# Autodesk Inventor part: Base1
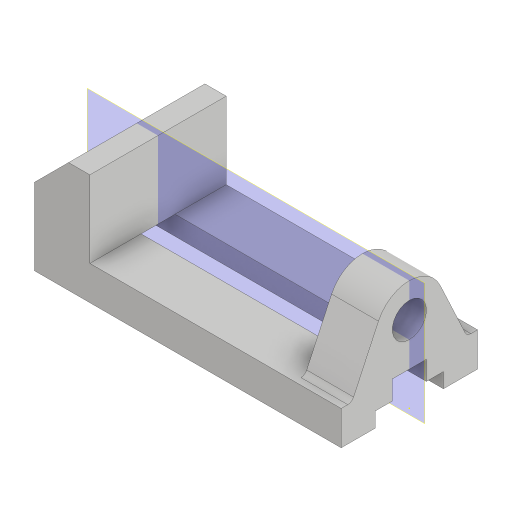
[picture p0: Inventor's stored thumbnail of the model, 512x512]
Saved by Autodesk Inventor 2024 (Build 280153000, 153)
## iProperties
Created: 2016-03
Part Number: Base1
Material: Generic
Document SubType Name: Modeling
Designer: Sandeep
Density: 1 g/cm^3
Appearance: Default
Author: Sandeep
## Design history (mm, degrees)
sketch "Sketch1"
  geometry: L1 (0, 0)-(0, 16); L2 (0, 16)-(118, 16); L3 (118, 16)-(118, 52); L4 (118, 52)-(144, 52); L5 (144, 52)-(144, 0); L6 (144, 0)-(0, 0)
  constraints: 12 end point, 3 perpendicular, 1 vertical
  dimensions: "d1" = 144 distance of L5.end L1.start; "d2" = 26 distance of L3.end L4.end; "d3" = 16 distance between parallel lines of L6 L2; "d4" = 36 distance between parallel lines of L2 L4
extrude "Extrusion1" new body sketch "Sketch1" stored distance "d5" = 64; taper "d6" = 0 deg
chamfer "Chamfer1" distance "d7" = 16; stored, may be unused: second distance "d8" = 16, angle "d9" = 45 deg
sketch "Sketch5"
  geometry: L1 (-16, 5.02)-(-42.762, 17.499); L2 (-42.762, 46.501)-(-16, 58.98); L3 (-52, 64)-(-52, 0) reference; L4 (-16, 32)-(-54.774, 32); L5 (-52, 64)-(-16, 64) reference; L6 (-16, 64)-(-16, 0) reference; L7 (-16, 5.02)-(-16, 58.98); L8 (0, 64)-(0, 0) reference; A1 r 16 centre (-36, 32) between (-42.762, 46.501) and (-42.762, 17.499); 1 further point
  constraints: 8 end point, 3 point on line, 3 tangent, 2 point on circle, 1 centre point, 1 collinear, 1 horizontal, 1 other
  dimensions: "d21" = 50 deg angle of L2 L1; "d22" = 36 distance from line of L8 A1.centre
extrude "Extrusion2" join sketch "Sketch5" distance "d23" = 22; taper "d24" = 0 deg
fillet "Fillet1" dims "d25" = 3
sketch "Sketch6"
  geometry: L1 (-36, 64)-(-36, 0) reference; C1 r 8 at (-36, 32); A1 r 16 centre (-36, 32) between (-42.762, 46.501) and (-42.762, 17.499) reference; 1 further point
  constraints: 1 centre point, 1 concentric, 1 midpoint
  dimensions: "d26" = 16 diameter of C1
extrude "Extrusion3" cut sketch "Sketch6" distance "d27" = 22; taper "d28" = 0 deg
sketch "Sketch7"
  geometry: L1 (0, 0)-(0, 64) reference; L2 (0, 16)-(-7, 16); L3 (-7, 16)-(-7, 24); L4 (-7, 24)-(-16, 24); L5 (-16, 3.109)-(-16, 60.891) reference; L6 (-16, 24)-(-16, 40); L7 (-7, 40)-(-7, 48); L8 (-7, 48)-(0, 48); L9 (0, 48)-(0, 16); L10 (-7, 40)-(-16, 40); L11 (-44, 32)-(-36, 32); 1 further point
  constraints: 18 end point, 6 point on line, 4 perpendicular, 2 horizontal, 1 collinear, 1 horizontal alignment, 4 other
  dimensions: "d29" = 32 distance between parallel lines of L2 L8; "d30" = 7 distance of L7.end L8.end; "d45" = 16 distance between parallel lines of L10 L4
extrude "Extrusion4" cut sketch "Sketch7" distance "d31" = 167.75; taper "d32" = 0 deg
sketch "Sketch8"
  geometry: L1 (144, 0)-(144, -16) reference; L2 (0, 0)-(144, 0) reference; L3 (0, -16)-(0, 0) reference; 3 further points
  dimensions: "d33" = 70 distance of point (108, -10) point (38, -10); "d35" = 10 distance from line of L2 point (108, -10); "d36" = 10 distance from line of L2 point (38, -10); "d46" = 38 distance from line of L3 point (38, -10)
hole "Hole1" sketch "Sketch8" diameter "d37" = 4.917; stored, may be unused: countersink angle "d41" = 90 deg, drill point angle "d43" = 118 deg; dims "d38" = 12, "d39" = 4, "d40" = 2, "d42" = 10
workplane "Work Plane1"
mirror "Mirror1"
body "Solid1"
sketch "Sketch4"
  geometry: 1 further point
other parameters: "d10" = 16, "d13" = 7, "d14" = 16, "d44" = -32
